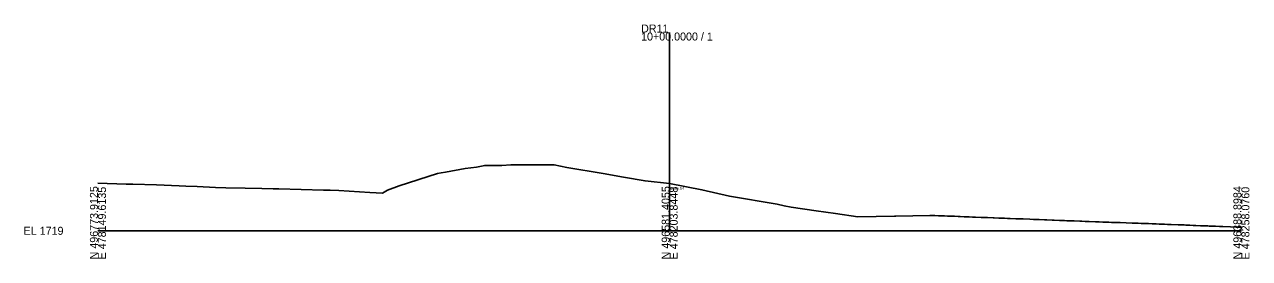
# Model space of a CAD drawing. Extents: x -26 to 478350, y -10 to 496623.
# Drawn here: x -25.7 to 402.8, y -9.7 to 72.2 of the extents above; entities that cross this region are included whole.
import ezdxf

# ---------------------------------------------------------------- set-up
doc = ezdxf.new("R2010")
doc.units = 0
for name, color, linetype in [('Exist Cross Section Cell', 7, 'Continuous'), ('Exist XS Center Line Elevation Label', 7, 'Continuous'), ('Exist XS Ground Line', 7, 'Continuous'), ('Scratch_Level_5', 7, 'Continuous')]:
    doc.layers.add(name, color=color, linetype=linetype)

msp = doc.modelspace()

# ---------------------------------------------------------------- linework, layer by layer
at = {"layer": 'Exist Cross Section Cell'}
for p, q in [((200, 0), (200, 69.37)), ((0, 0), (200, 0)), ((200, 0), (400, 0))]:
    msp.add_line(p, q, dxfattribs=at)
at = {"layer": 'Exist XS Ground Line'}
msp.add_lwpolyline([(0, 16.7), (9.89, 16.35), (12.25, 16.29), (20.47, 16.08), (28.47, 15.69), (30.72, 15.57), (34.74, 15.44), (41.11, 15.11), (44.68, 15.06), (51.5, 14.9), (57.36, 14.8), (61.35, 14.69), (62.16, 14.66), (63.32, 14.66), (78.92, 14.24), (80.38, 14.24), (81.27, 14.23), (84.24, 14.05), (95.12, 13.42), (99.5, 13.19), (101.29, 14.23), (105.37, 15.72), (118.81, 19.99), (120.1, 20.27), (121.55, 20.52), (128.48, 21.81), (132.43, 22.27), (135.3, 22.85), (141.27, 22.86), (144.39, 23.11), (152.77, 23.12), (153.92, 23.12), (159.56, 23.04), (164.08, 22.13), (176.69, 20.02), (183.88, 18.75), (191.38, 17.44), (200, 16.54), (211.31, 14.36), (220.89, 12.15), (237.57, 9.35), (240.06, 8.76), (242.56, 8.23), (251.3, 7.02), (258.04, 6.04), (265.83, 4.85), (278.7, 5.06), (279.15, 5.07), (291.06, 5.33), (292.74, 5.33), (293.99, 5.28), (294.7, 5.25), (296.2, 5.2), (297.23, 5.16), (297.68, 5.14), (299.64, 5.07), (300.92, 5.01), (301.63, 4.99), (303.02, 4.94), (304.38, 4.88), (304.78, 4.87), (305.97, 4.82), (306.99, 4.78), (309.02, 4.7), (309.86, 4.66), (311.15, 4.61), (313.14, 4.53), (313.52, 4.52), (315.12, 4.46), (315.58, 4.44), (317.15, 4.38), (318.18, 4.34), (319.17, 4.3), (321.04, 4.23), (322.72, 4.16), (323.62, 4.13), (325.97, 4.04), (327.27, 3.99), (328.56, 3.94), (329.3, 3.91), (331.17, 3.84), (331.92, 3.81), (333.75, 3.74), (334.47, 3.71), (336.35, 3.64), (338.11, 3.57), (338.95, 3.54), (341.06, 3.46), (341.55, 3.44), (343.47, 3.37), (344.14, 3.34), (345.36, 3.3), (346.74, 3.25), (348.99, 3.16), (349.53, 3.14), (350.23, 3.12), (351.56, 3.07), (351.93, 3.06), (353.59, 3), (354.53, 2.96), (355.62, 2.92), (357.13, 2.87), (357.65, 2.85), (359.74, 2.78), (361.76, 2.71), (362.41, 2.68), (363.92, 2.63), (364.92, 2.6), (367, 2.52), (367.52, 2.5), (368.8, 2.46), (369.5, 2.43), (370.2, 2.41), (371.2, 2.37), (373.16, 2.3), (374.17, 2.26), (375.45, 2.21), (377.91, 2.11), (379.93, 2.03), (380.51, 2), (381.96, 1.94), (383.16, 1.89), (384.1, 1.85), (385.72, 1.79), (386.11, 1.77), (387.21, 1.73), (388.3, 1.68), (388.74, 1.67), (390.9, 1.58), (392.39, 1.53), (393.5, 1.48), (396.23, 1.37), (398.16, 1.3), (398.69, 1.29), (400, 1.24)], dxfattribs=at)
at = {"layer": 'Scratch_Level_5'}
msp.add_lwpolyline([(0, 16.7), (9.89, 16.35), (12.25, 16.29), (20.47, 16.08), (28.47, 15.69), (30.72, 15.57), (34.74, 15.44), (41.11, 15.11), (44.68, 15.06), (51.5, 14.9), (57.36, 14.8), (61.35, 14.69), (62.16, 14.66), (63.32, 14.66), (78.92, 14.24), (80.38, 14.24), (81.27, 14.23), (84.24, 14.05), (95.12, 13.42), (99.5, 13.19), (101.29, 14.23), (105.37, 15.72), (118.81, 19.99), (120.1, 20.27), (121.55, 20.52), (128.48, 21.81), (132.43, 22.27), (135.3, 22.85), (141.27, 22.86), (144.39, 23.11), (152.77, 23.12), (153.92, 23.12), (159.56, 23.04), (164.08, 22.13), (176.69, 20.02), (183.88, 18.75), (191.38, 17.44), (200, 16.54), (211.31, 14.36), (220.89, 12.15), (237.57, 9.35), (240.06, 8.76), (242.56, 8.23), (251.3, 7.02), (258.04, 6.04), (265.83, 4.85), (278.7, 5.06), (279.15, 5.07), (291.06, 5.33), (292.74, 5.33), (293.99, 5.28), (294.7, 5.25), (296.2, 5.2), (297.23, 5.16), (297.68, 5.14), (299.64, 5.07), (300.92, 5.01), (301.63, 4.99), (303.02, 4.94), (304.38, 4.88), (304.78, 4.87), (305.97, 4.82), (306.99, 4.78), (309.02, 4.7), (309.86, 4.66), (311.15, 4.61), (313.14, 4.53), (313.52, 4.52), (315.12, 4.46), (315.58, 4.44), (317.15, 4.38), (318.18, 4.34), (319.17, 4.3), (321.04, 4.23), (322.72, 4.16), (323.62, 4.13), (325.97, 4.04), (327.27, 3.99), (328.56, 3.94), (329.3, 3.91), (331.17, 3.84), (331.92, 3.81), (333.75, 3.74), (334.47, 3.71), (336.35, 3.64), (338.11, 3.57), (338.95, 3.54), (341.06, 3.46), (341.55, 3.44), (343.47, 3.37), (344.14, 3.34), (345.36, 3.3), (346.74, 3.25), (348.99, 3.16), (349.53, 3.14), (350.23, 3.12), (351.56, 3.07), (351.93, 3.06), (353.59, 3), (354.53, 2.96), (355.62, 2.92), (357.13, 2.87), (357.65, 2.85), (359.74, 2.78), (361.76, 2.71), (362.41, 2.68), (363.92, 2.63), (364.92, 2.6), (367, 2.52), (367.52, 2.5), (368.8, 2.46), (369.5, 2.43), (370.2, 2.41), (371.2, 2.37), (373.16, 2.3), (374.17, 2.26), (375.45, 2.21), (377.91, 2.11), (379.93, 2.03), (380.51, 2), (381.96, 1.94), (383.16, 1.89), (384.1, 1.85), (385.72, 1.79), (386.11, 1.77), (387.21, 1.73), (388.3, 1.68), (388.74, 1.67), (390.9, 1.58), (392.39, 1.53), (393.5, 1.48), (396.23, 1.37), (398.16, 1.3), (398.69, 1.29), (400, 1.24)], dxfattribs=at)

# ---------------------------------------------------------------- texts
at = {"layer": 'Exist Cross Section Cell'}
for s, p in [('10+00.0000 / 1', (190, 66.57)), ('DR11', (190, 69.37)), ('EL 1719', (-26, -1.4))]:
    msp.add_text(s, height=2.8, dxfattribs=at).set_placement(p)
for s, p in [('N 496773.9125', (0, -10)), ('E 478149.6135', (2.8, -10)), ('N 496581.4055', (200, -10)), ('E 478203.8448', (202.8, -10)), ('N 496388.8984', (400, -10)), ('E 478258.0760', (402.8, -10))]:
    msp.add_text(s, height=2.8, rotation=90, dxfattribs=at).set_placement(p)
at = {"layer": 'Exist XS Center Line Elevation Label'}
msp.add_text('1735.54', height=1, dxfattribs=at).set_placement((200.07, 14.35))

doc.saveas('drawing.dxf')
